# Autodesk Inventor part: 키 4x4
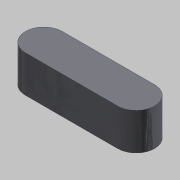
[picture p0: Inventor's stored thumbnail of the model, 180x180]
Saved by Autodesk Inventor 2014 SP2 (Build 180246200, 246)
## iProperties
Created: 2016-04
Part Number: 키 4x4
Document SubType Name: Modeling
Designer: mdu
Density: 7.86 g/cm^3
Mass: 1.65269 g
Surface Area: 2.35398 cm^2
Volume: 0.210265 cm^3
Material: 강철, 연강
Appearance: 강철 - 광택
Author: mdu
Revision Number: 1
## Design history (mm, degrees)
sketch "스케치1"
  geometry: L1 (-5, -2)-(5, -2); L2 (5, 2)-(-5, 2); A1 r 2 centre (5, 0) between (5, -2) and (5, 2); A2 r 2 centre (-5, 0) between (-5, 2) and (-5, -2); 2 further points
  constraints: 4 end point, 4 point on circle, 4 tangent, 2 centre point, 1 horizontal, 1 horizontal alignment, 1 midpoint, 1 parallel, 1 vertical alignment
  dimensions: "d0" = 4 distance between parallel lines of L1 L2; "d1" = 14 dimension on A1 A2
extrude "돌출1" new body sketch "스케치1" stored distance "d2" = 4; taper "d3" = 0 deg
node "솔리드1"
